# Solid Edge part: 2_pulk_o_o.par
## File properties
Author: Romil
Template: iso part.par
Last saved by: Romil
Revision: 33
Application: Solid Edge
Accuracy: 0.990
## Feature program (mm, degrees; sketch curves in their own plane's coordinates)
sketch used by "unnamed Protrusion 1" plane through (0, 0, 0) normal (1, 0, 0) x-axis (0, 1, 0)
extrude "unnamed Protrusion 1" add finite 1.8 symmetric
sketch for "ExtrudedProtrusion_6" plane through (0, 0, 0) normal (1, 0, 0) x-axis (0, 1, 0)
extrude "ExtrudedProtrusion_6" add finite 15.6 symmetric
sketch for "ExtrudedProtrusion_7" plane through (7.8, 0, 0) normal (1, 0, 0) x-axis (0, -1, 0)
extrude "ExtrudedProtrusion_7" add finite 0.8 along -normal
sketch for "ExtrudedCutout_5" plane through (7.8, 0, 0) normal (1, 0, 0) x-axis (0, -1, 0)
extrude "ExtrudedCutout_5" cut finite 25.2083 along -normal
fillet "Round_10" radius 0.3
sketch for "ExtrudedCutout_7" plane through (7.8, 0, 0) normal (1, 0, 0) x-axis (0, 0, 1)
extrude "ExtrudedCutout_7" cut finite 3 along -normal
sketch for "ExtrudedProtrusion_8" #1 plane through (0, 0, 0) normal (1, 0, 0) x-axis (0, 1, 0)
sketch for "ExtrudedProtrusion_8" #2 plane through (0, 0, 0) normal (1, 0, 0) x-axis (0, 1, 0)
sketch for "ExtrudedProtrusion_8" #3 plane through (0, 0, 0) normal (1, 0, 0) x-axis (0, 1, 0)
  arc centre (0.9762, 1.1209) radius 0.9136 from (1.8598, 1.3533) to (1.085, 2.028) ccw
  line (1.085, 2.028) -> (1.0328, 1.968)
  arc centre (0, 0) radius 2.2226 from (1.8076, 1.2933) to (1.0328, 1.968) ccw
  line (1.8076, 1.2933) -> (1.8598, 1.3533)
sketch for "ExtrudedProtrusion_8" #4 plane through (0, 0, 0) normal (1, 0, 0) x-axis (0, 1, 0)
  arc centre (0, 0) radius 2.2226 from (1.8076, -1.2933) to (1.0328, -1.968) cw
  line (1.085, -2.028) -> (1.0328, -1.968)
  arc centre (0.9762, -1.1209) radius 0.9136 from (1.8598, -1.3533) to (1.085, -2.028) cw
  line (1.8076, -1.2933) -> (1.8598, -1.3533)
extrude "ExtrudedProtrusion_8" add finite 2.5 along +normal
fillet "unnamed Round 1"
mirror "unnamed Mirror 1" of "ExtrudedProtrusion_8", "unnamed Round 1" about plane through (3.9, 0, 0) normal (1, 0, 0)
extrude "unnamed Protrusion 2" add finite 2.5
fillet "unnamed Round 2"
mirror "unnamed Mirror 2" of "unnamed Mirror 1", "unnamed Round 1", "ExtrudedProtrusion_8", "ExtrudedCutout_7", "Round_10", "ExtrudedCutout_5", "ExtrudedProtrusion_7" about plane through (0, 0, 0) normal (1, 0, 0)
extrude "unnamed Protrusion 3" add finite 0.8
extrude "unnamed Cutout 1" cut finite 25.2083
fillet "unnamed Round 3"
extrude "unnamed Cutout 2" cut finite 3
extrude "unnamed Protrusion 4" add finite 2.5
fillet "unnamed Round 4"
sketch for "unnamed Protrusion 5" #2
  circle centre (0, 0) radius 2.6
sketch for "unnamed Protrusion 5" #3
  circle centre (0, 0) radius 2.6
extrude "unnamed Protrusion 5" add finite 2.5
fillet "unnamed Round 5"
sketch for "ExtrudedCutout_10" plane through (0, 0, 0) normal (0, 0, 1) x-axis (1, 0, 0)
extrude "ExtrudedCutout_10" cut finite 52.2767 symmetric
fillet "unnamed Round 6"
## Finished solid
Body 1: solid body, 93 faces, 276 edges, 184 vertices.
  Faces by surface: cylinder 45, plane 24, torus 24
  Edges by curve: line 112, circle 92, intersection 72
Bounding box of the edges (mm; curved faces can reach further): 15.600 x 6.200 x 6.119, from (-7.8, -3.1, -3.0594) to (7.8, 3.1, 3.0594).
Cylindrical faces by radius (mm): R0.4 x12, R0.9136 x24, R1.7 x1, R2.35 x2, R2.6 x4, R3.1 x2
Toroidal faces (ring radius, tube radius in mm): R0.6136 r0.3 x16, R2.3 r0.3 x8
Planar faces by outward normal: +x 6, +y 2, +z 4, -x 6, -y 2, -z 4
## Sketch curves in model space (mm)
circle centre (0, 0, 0) radius 1.4
circle centre (0, 0, 0) radius 2.35
circle centre (0, 0, 0) radius 3.1
line (0, 4.3566, -0.4) -> (0, 4.3566, 0.4)
line (0, 4.3566, 0.4) -> (0, -4.3566, 0.4)
line (0, -4.3566, 0.4) -> (0, -4.3566, -0.4)
line (0, -4.3566, -0.4) -> (0, 4.3566, -0.4)
line (0, -1.085, 2.028) -> (0, -1.0328, 1.968)
arc centre (0, -0.9762, 1.1209) radius 0.9136 from (0, -1.8598, 1.3533) through (0, -1.5762, 1.8098) to (0, -1.085, 2.028)
line (0, -1.8076, 1.2933) -> (0, -1.8598, 1.3533)
arc centre (0, 0, 0) radius 2.2226 from (0, -1.8076, 1.2933) through (0, -1.4597, 1.6761) to (0, -1.0328, 1.968)
line (0, 1.085, 2.028) -> (0, 1.0328, 1.968)
arc centre (0, 0.9762, 1.1209) radius 0.9136 from (0, 1.8598, 1.3533) through (0, 1.5762, 1.8098) to (0, 1.085, 2.028)
line (0, 1.8076, 1.2933) -> (0, 1.8598, 1.3533)
arc centre (0, 0, 0) radius 2.2226 from (0, 1.8076, 1.2933) through (0, 1.4597, 1.6761) to (0, 1.0328, 1.968)
line (0, -1.085, -2.028) -> (0, -1.0328, -1.968)
arc centre (0, -0.9762, -1.1209) radius 0.9136 from (0, -1.8598, -1.3533) through (0, -1.5762, -1.8098) to (0, -1.085, -2.028)
line (0, -1.8076, -1.2933) -> (0, -1.8598, -1.3533)
arc centre (0, 0, 0) radius 2.2226 from (0, -1.8076, -1.2933) through (0, -1.4597, -1.6761) to (0, -1.0328, -1.968)
line (0, 1.085, -2.028) -> (0, 1.0328, -1.968)
arc centre (0, 0.9762, -1.1209) radius 0.9136 from (0, 1.8598, -1.3533) through (0, 1.5762, -1.8098) to (0, 1.085, -2.028)
line (0, 1.8076, -1.2933) -> (0, 1.8598, -1.3533)
arc centre (0, 0, 0) radius 2.2226 from (0, 1.8076, -1.2933) through (0, 1.4597, -1.6761) to (0, 1.0328, -1.968)
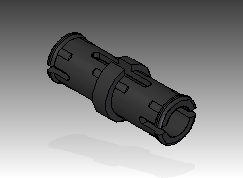
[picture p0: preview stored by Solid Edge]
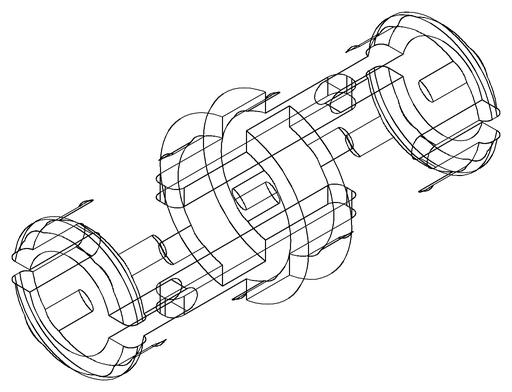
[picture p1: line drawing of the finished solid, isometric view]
